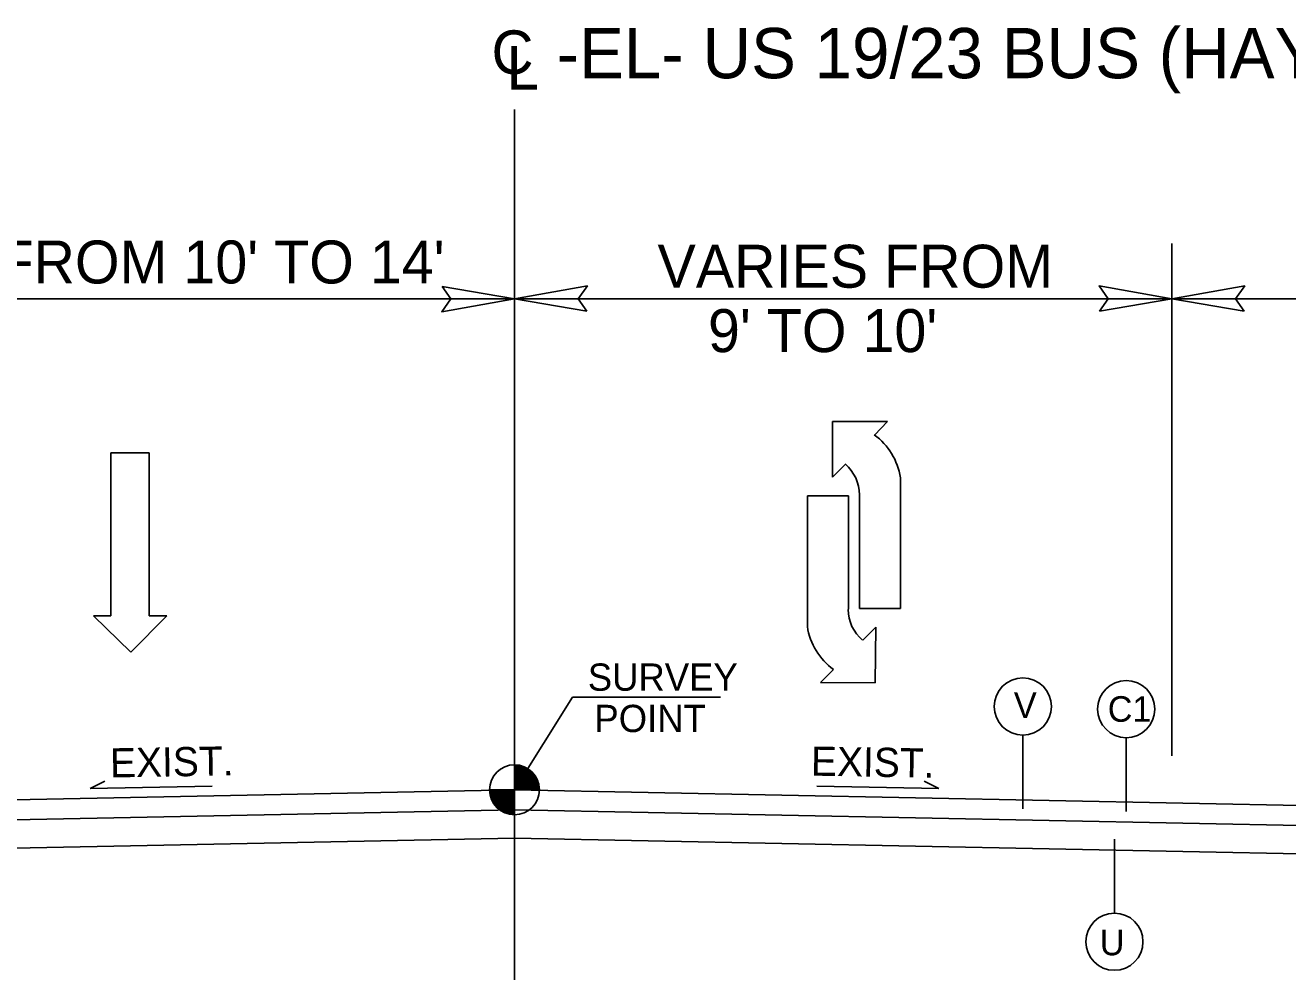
# Model space of a CAD drawing. Extents: x 1022283 to 1026986, y 174822 to 180471.
# Drawn here: x 1023625.2 to 1024095.7, y 178947.4 to 179303 of the extents above; entities that cross this region are included whole.
import ezdxf

# ---------------------------------------------------------------- set-up
doc = ezdxf.new("R2010")
doc.units = 0
for name, color, linetype in [('Default', 7, 'Continuous'), ('Prop Dimension', 7, 'Continuous'), ('Prop Lane Arrow CELL', 7, 'Continuous'), ('Prop Terminator CELL', 7, 'Continuous'), ('Typical Berm Information CELL', 7, 'Continuous'), ('Typical Grade Point Symbol CELL', 7, 'Continuous'), ('Typical ID Circle CELL', 7, 'Continuous'), ('Typical Text Centerline CELL', 7, 'Continuous'), ('Typical Text Grade Point CELL', 7, 'Continuous'), ('Typical Text ID Circle CELL', 7, 'Continuous')]:
    doc.layers.add(name, color=color, linetype=linetype)

# ---------------------------------------------------------------- blocks, each defined once
blk = doc.blocks.new('Lane Arrow Through')
at = {"layer": 'Prop Lane Arrow CELL'}
for p, q in [((-3.15, 1.6), (-3.15, 3.1)), ((-3.15, 3.1), (0, 0)), ((-17.15, 1.6), (-3.15, 1.6)), ((-17.15, -1.7), (-17.15, 1.6)), ((0, 0), (-3.15, -3.2)), ((-3.15, -1.7), (-17.15, -1.7)), ((-3.15, -3.2), (-3.15, -1.7))]:
    blk.add_line(p, q, dxfattribs=at)

msp = doc.modelspace()

# ---------------------------------------------------------------- linework, layer by layer
at = {"layer": 'Default'}
for p, q in [((1024052.49, 179030.88), (1024052.49, 179221.7)), ((1023299.79, 179201.13), (1023807.5, 179201.13)), ((1023807.5, 179201.13), (1024315.21, 179201.13)), ((1024315.21, 179201.13), (1023807.5, 179201.13))]:
    msp.add_line(p, q, dxfattribs=at)
at = {"layer": 'Prop Dimension'}
for p, q in [((1023807.5, 179212.25), (1023807.5, 179271.7)), ((1023807.5, 178947.45), (1023807.5, 179212.25)), ((1023829.15, 179052.68), (1023807.5, 179018.24)), ((1023829.15, 179052.68), (1023807.5, 179018.24)), ((1023312.45, 179008.34), (1023807.5, 179018.24)), ((1023312.45, 179008.34), (1023807.5, 179018.24)), ((1024315.21, 179008.08), (1023807.5, 179018.24)), ((1024315.21, 179008.08), (1023807.5, 179018.24)), ((1023312.45, 179000.84), (1023807.5, 179010.74)), ((1023312.45, 179000.84), (1023807.5, 179010.74)), ((1024315.21, 179000.58), (1023807.5, 179010.74)), ((1024315.21, 179000.58), (1023807.5, 179010.74)), ((1023299.79, 178990), (1023807.5, 179000.15)), ((1024315.21, 178990), (1023807.5, 179000.15))]:
    msp.add_line(p, q, dxfattribs=at)
at = {"layer": 'Prop Lane Arrow CELL'}
for p, q in [((1023946.5, 179155.44), (1023925.95, 179155.44)), ((1023925.95, 179155.44), (1023925.95, 179134.66)), ((1023941.65, 179150.36), (1023946.5, 179155.44)), ((1023925.95, 179134.66), (1023930.8, 179139.51)), ((1023951.35, 179085.72), (1023951.35, 179134.43)), ((1023916.72, 179127.74), (1023916.72, 179079.02)), ((1023931.96, 179127.74), (1023916.72, 179127.74)), ((1023931.96, 179085.48), (1023931.96, 179127.74)), ((1023931.96, 179127.74), (1023931.96, 179085.48)), ((1023936.11, 179127.97), (1023936.11, 179085.72)), ((1023936.11, 179085.72), (1023951.35, 179085.72)), ((1023942.12, 179078.79), (1023937.27, 179073.94)), ((1023941.88, 179058.01), (1023942.12, 179078.79)), ((1023926.41, 179063.09), (1023921.57, 179058.24)), ((1023921.57, 179058.24), (1023941.88, 179058.01))]:
    msp.add_line(p, q, dxfattribs=at)
for centre, radius, start, end in [((1023927.32, 179130.84), 24.26, 8.6761, 53.9878), ((1023920.93, 179128.08), 15.12, 360, 49.6582), ((1023947, 179085.44), 15.12, 180, 229.6582), ((1023940.62, 179082.68), 24.26, 188.6761, 233.9878)]:
    msp.add_arc(centre, radius, start, end, dxfattribs=at)
at = {"layer": 'Prop Terminator CELL'}
for points in [[(1023780.5, 179205.78), (1023807.5, 179201.13), (1023780.35, 179196.33), (1023783.8, 179201.13)], [(1023834.5, 179196.48), (1023807.5, 179201.13), (1023834.65, 179205.93), (1023831.2, 179201.13)], [(1023834.5, 179196.48), (1023807.5, 179201.13), (1023834.65, 179205.93), (1023831.2, 179201.13)], [(1024025.49, 179196.48), (1024052.49, 179201.13), (1024025.34, 179205.93), (1024028.79, 179201.13)], [(1024079.49, 179196.48), (1024052.49, 179201.13), (1024079.64, 179205.93), (1024076.19, 179201.13)]]:
    msp.add_lwpolyline(points, close=True, dxfattribs=at)
at = {"layer": 'Typical Berm Information CELL'}
for p, q in [((1023654.85, 179021.45), (1023649.33, 179018.68)), ((1023960.16, 179021.45), (1023965.68, 179018.68)), ((1023649.33, 179018.68), (1023694.85, 179019.6)), ((1023965.68, 179018.68), (1023920.16, 179019.6))]:
    msp.add_line(p, q, dxfattribs=at)
at = {"layer": 'Typical Grade Point Symbol CELL'}
for p, q in [((1023807.5, 179018.24), (1023807.5, 179027.53)), ((1023807.5, 179018.24), (1023807.5, 179027.53)), ((1023798.21, 179018.24), (1023807.5, 179018.24)), ((1023798.21, 179018.24), (1023807.5, 179018.24)), ((1023807.48, 179008.94), (1023807.5, 179018.24)), ((1023807.5, 179018.24), (1023807.48, 179008.94)), ((1023807.48, 179008.94), (1023807.5, 179018.24)), ((1023807.5, 179018.24), (1023807.48, 179008.94)), ((1023816.8, 179018.24), (1023807.5, 179018.24)), ((1023816.8, 179018.24), (1023807.5, 179018.24))]:
    msp.add_line(p, q, dxfattribs=at)
for points in [[(1023807.59, 179027.53), (1023807.59, 179027.53), (1023807.59, 179018.24)], [(1023807.59, 179027.53), (1023807.59, 179027.53), (1023807.59, 179018.24)], [(1023807.77, 179027.53), (1023807.77, 179018.24)], [(1023807.77, 179027.53), (1023807.77, 179018.24)], [(1023807.96, 179027.51), (1023807.96, 179018.24)], [(1023807.96, 179027.51), (1023807.96, 179018.24)], [(1023808.14, 179027.51), (1023808.14, 179018.24)], [(1023808.14, 179027.51), (1023808.14, 179018.24)], [(1023808.33, 179027.49), (1023808.33, 179018.24)], [(1023808.33, 179027.49), (1023808.33, 179018.24)], [(1023808.52, 179027.47), (1023808.52, 179018.24)], [(1023808.52, 179027.47), (1023808.52, 179018.24)], [(1023808.7, 179027.45), (1023808.7, 179018.24)], [(1023808.7, 179027.45), (1023808.7, 179018.24)], [(1023808.89, 179027.43), (1023808.89, 179018.24)], [(1023808.89, 179027.43), (1023808.89, 179018.24)], [(1023809.07, 179027.41), (1023809.07, 179018.24)], [(1023809.07, 179027.41), (1023809.07, 179018.24)], [(1023809.26, 179027.37), (1023809.26, 179018.24)], [(1023809.26, 179027.37), (1023809.26, 179018.24)], [(1023809.45, 179027.33), (1023809.45, 179018.24)], [(1023809.45, 179027.33), (1023809.45, 179018.24)], [(1023809.63, 179027.29), (1023809.63, 179018.24)], [(1023809.63, 179027.29), (1023809.63, 179018.24)], [(1023809.82, 179027.25), (1023809.82, 179018.24)], [(1023809.82, 179027.25), (1023809.82, 179018.24)], [(1023810, 179027.18), (1023810, 179018.24)], [(1023810, 179027.18), (1023810, 179018.24)], [(1023810.19, 179027.14), (1023810.19, 179018.24)], [(1023810.19, 179027.14), (1023810.19, 179018.24)], [(1023810.38, 179027.08), (1023810.38, 179018.24)], [(1023810.38, 179027.08), (1023810.38, 179018.24)], [(1023810.56, 179027.02), (1023810.56, 179018.24)], [(1023810.56, 179027.02), (1023810.56, 179018.24)], [(1023810.75, 179026.96), (1023810.75, 179018.24)], [(1023810.75, 179026.96), (1023810.75, 179018.24)], [(1023810.93, 179026.87), (1023810.93, 179018.24)], [(1023810.93, 179026.87), (1023810.93, 179018.24)], [(1023811.12, 179026.79), (1023811.12, 179018.24)], [(1023811.12, 179026.79), (1023811.12, 179018.24)], [(1023811.31, 179026.71), (1023811.31, 179018.24)], [(1023811.31, 179026.71), (1023811.31, 179018.24)], [(1023811.49, 179026.63), (1023811.49, 179018.24)], [(1023811.49, 179026.63), (1023811.49, 179018.24)], [(1023811.68, 179026.54), (1023811.68, 179018.24)], [(1023811.68, 179026.54), (1023811.68, 179018.24)], [(1023811.86, 179026.44), (1023811.86, 179018.24)], [(1023811.86, 179026.44), (1023811.86, 179018.24)], [(1023812.05, 179026.34), (1023812.05, 179018.24)], [(1023812.05, 179026.34), (1023812.05, 179018.24)], [(1023812.23, 179026.23), (1023812.23, 179018.24)], [(1023812.23, 179026.23), (1023812.23, 179018.24)], [(1023812.42, 179026.13), (1023812.42, 179018.24)], [(1023812.42, 179026.13), (1023812.42, 179018.24)], [(1023812.61, 179026.01), (1023812.61, 179018.24)], [(1023812.61, 179026.01), (1023812.61, 179018.24)], [(1023812.79, 179025.88), (1023812.79, 179018.24)], [(1023812.79, 179025.88), (1023812.79, 179018.24)], [(1023812.98, 179025.74), (1023812.98, 179018.24)], [(1023812.98, 179025.74), (1023812.98, 179018.24)], [(1023813.16, 179025.61), (1023813.16, 179018.24)], [(1023813.16, 179025.61), (1023813.16, 179018.24)], [(1023813.35, 179025.47), (1023813.35, 179018.24)], [(1023813.35, 179025.47), (1023813.35, 179018.24)], [(1023813.54, 179025.3), (1023813.54, 179018.24)], [(1023813.54, 179025.3), (1023813.54, 179018.24)], [(1023813.72, 179025.14), (1023813.72, 179018.24)], [(1023813.72, 179025.14), (1023813.72, 179018.24)], [(1023813.91, 179024.97), (1023813.91, 179018.24)], [(1023813.91, 179024.97), (1023813.91, 179018.24)], [(1023814.09, 179024.79), (1023814.09, 179018.24)], [(1023814.09, 179024.79), (1023814.09, 179018.24)], [(1023814.28, 179024.6), (1023814.28, 179018.24)], [(1023814.28, 179024.6), (1023814.28, 179018.24)], [(1023814.47, 179024.39), (1023814.47, 179018.24)], [(1023814.47, 179024.39), (1023814.47, 179018.24)], [(1023814.65, 179024.17), (1023814.65, 179018.24)], [(1023814.65, 179024.17), (1023814.65, 179018.24)], [(1023814.84, 179023.94), (1023814.84, 179018.24)], [(1023814.84, 179023.94), (1023814.84, 179018.24)], [(1023815.02, 179023.69), (1023815.02, 179018.24)], [(1023815.02, 179023.69), (1023815.02, 179018.24)], [(1023815.21, 179023.42), (1023815.21, 179018.24)], [(1023815.21, 179023.42), (1023815.21, 179018.24)], [(1023815.4, 179023.13), (1023815.4, 179018.24)], [(1023815.4, 179023.13), (1023815.4, 179018.24)], [(1023815.58, 179022.83), (1023815.58, 179018.24)], [(1023815.58, 179022.83), (1023815.58, 179018.24)], [(1023815.77, 179022.49), (1023815.77, 179018.24)], [(1023815.77, 179022.49), (1023815.77, 179018.24)], [(1023815.95, 179022.1), (1023815.95, 179018.24)], [(1023815.95, 179022.1), (1023815.95, 179018.24)], [(1023816.14, 179021.67), (1023816.14, 179018.24)], [(1023816.14, 179021.67), (1023816.14, 179018.24)], [(1023816.32, 179021.15), (1023816.32, 179018.24)], [(1023816.32, 179021.15), (1023816.32, 179018.24)], [(1023798.25, 179018.24), (1023798.25, 179017.23)], [(1023798.25, 179018.24), (1023798.25, 179017.23)], [(1023798.44, 179018.24), (1023798.44, 179016.13)], [(1023798.44, 179018.24), (1023798.44, 179016.13)], [(1023798.62, 179018.24), (1023798.62, 179015.47)], [(1023798.62, 179018.24), (1023798.62, 179015.47)], [(1023798.81, 179018.24), (1023798.81, 179014.91)], [(1023798.81, 179018.24), (1023798.81, 179014.91)], [(1023798.99, 179018.24), (1023798.99, 179014.48)], [(1023798.99, 179018.24), (1023798.99, 179014.48)], [(1023799.18, 179018.24), (1023799.18, 179014.09)], [(1023799.18, 179018.24), (1023799.18, 179014.09)], [(1023799.37, 179018.24), (1023799.37, 179013.74)], [(1023799.37, 179018.24), (1023799.37, 179013.74)], [(1023799.55, 179018.24), (1023799.55, 179013.41)], [(1023799.55, 179018.24), (1023799.55, 179013.41)], [(1023799.74, 179018.24), (1023799.74, 179013.12)], [(1023799.74, 179018.24), (1023799.74, 179013.12)], [(1023799.92, 179018.24), (1023799.92, 179012.85)], [(1023799.92, 179018.24), (1023799.92, 179012.85)], [(1023800.11, 179018.24), (1023800.11, 179012.6)], [(1023800.11, 179018.24), (1023800.11, 179012.6)], [(1023800.3, 179018.24), (1023800.3, 179012.37)], [(1023800.3, 179018.24), (1023800.3, 179012.37)], [(1023800.48, 179018.24), (1023800.48, 179012.15)], [(1023800.48, 179018.24), (1023800.48, 179012.15)], [(1023800.67, 179018.24), (1023800.67, 179011.94)], [(1023800.67, 179018.24), (1023800.67, 179011.94)], [(1023800.85, 179018.24), (1023800.85, 179011.73)], [(1023800.85, 179018.24), (1023800.85, 179011.73)], [(1023801.04, 179018.24), (1023801.04, 179011.55)], [(1023801.04, 179018.24), (1023801.04, 179011.55)], [(1023801.23, 179018.24), (1023801.23, 179011.38)], [(1023801.23, 179018.24), (1023801.23, 179011.38)], [(1023801.41, 179018.24), (1023801.41, 179011.22)], [(1023801.41, 179018.24), (1023801.41, 179011.22)], [(1023801.6, 179018.24), (1023801.6, 179011.05)], [(1023801.6, 179018.24), (1023801.6, 179011.05)], [(1023801.78, 179018.24), (1023801.78, 179010.91)], [(1023801.78, 179018.24), (1023801.78, 179010.91)], [(1023801.97, 179018.24), (1023801.97, 179010.76)], [(1023801.97, 179018.24), (1023801.97, 179010.76)], [(1023802.15, 179018.24), (1023802.15, 179010.64)], [(1023802.15, 179018.24), (1023802.15, 179010.64)], [(1023802.34, 179018.24), (1023802.34, 179010.51)], [(1023802.34, 179018.24), (1023802.34, 179010.51)], [(1023802.53, 179018.24), (1023802.53, 179010.39)], [(1023802.53, 179018.24), (1023802.53, 179010.39)], [(1023802.71, 179018.24), (1023802.71, 179010.27)], [(1023802.71, 179018.24), (1023802.71, 179010.27)], [(1023802.9, 179018.24), (1023802.9, 179010.16)], [(1023802.9, 179018.24), (1023802.9, 179010.16)], [(1023803.08, 179018.24), (1023803.08, 179010.06)], [(1023803.08, 179018.24), (1023803.08, 179010.06)], [(1023803.27, 179018.24), (1023803.27, 179009.96)], [(1023803.27, 179018.24), (1023803.27, 179009.96)], [(1023803.46, 179018.24), (1023803.46, 179009.87)], [(1023803.46, 179018.24), (1023803.46, 179009.87)], [(1023803.64, 179018.24), (1023803.64, 179009.79)], [(1023803.64, 179018.24), (1023803.64, 179009.79)], [(1023803.83, 179018.24), (1023803.83, 179009.71)], [(1023803.83, 179018.24), (1023803.83, 179009.71)], [(1023804.01, 179018.24), (1023804.01, 179009.63)], [(1023804.01, 179018.24), (1023804.01, 179009.63)], [(1023804.2, 179018.24), (1023804.2, 179009.54)], [(1023804.2, 179018.24), (1023804.2, 179009.54)], [(1023804.39, 179018.24), (1023804.39, 179009.48)], [(1023804.39, 179018.24), (1023804.39, 179009.48)], [(1023804.57, 179018.24), (1023804.57, 179009.42)], [(1023804.57, 179018.24), (1023804.57, 179009.42)], [(1023804.76, 179018.24), (1023804.76, 179009.36)], [(1023804.76, 179018.24), (1023804.76, 179009.36)], [(1023804.94, 179018.24), (1023804.94, 179009.32)], [(1023804.94, 179018.24), (1023804.94, 179009.32)], [(1023805.13, 179018.24), (1023805.13, 179009.25)], [(1023805.13, 179018.24), (1023805.13, 179009.25)], [(1023805.32, 179018.24), (1023805.32, 179009.21)], [(1023805.32, 179018.24), (1023805.32, 179009.21)], [(1023805.5, 179018.24), (1023805.5, 179009.17)], [(1023805.5, 179018.24), (1023805.5, 179009.17)], [(1023805.69, 179018.24), (1023805.69, 179009.13)], [(1023805.69, 179018.24), (1023805.69, 179009.13)], [(1023805.87, 179018.24), (1023805.87, 179009.09)], [(1023805.87, 179018.24), (1023805.87, 179009.09)], [(1023806.06, 179018.24), (1023806.06, 179009.07)], [(1023806.06, 179018.24), (1023806.06, 179009.07)], [(1023806.24, 179018.24), (1023806.24, 179009.03)], [(1023806.24, 179018.24), (1023806.24, 179009.03)], [(1023806.43, 179018.24), (1023806.43, 179009.01)], [(1023806.43, 179018.24), (1023806.43, 179009.01)], [(1023806.62, 179018.24), (1023806.62, 179008.99)], [(1023806.62, 179018.24), (1023806.62, 179008.99)], [(1023806.8, 179018.24), (1023806.8, 179008.96)], [(1023806.8, 179018.24), (1023806.8, 179008.96)], [(1023806.99, 179018.24), (1023806.99, 179008.96)], [(1023806.99, 179018.24), (1023806.99, 179008.96)], [(1023807.17, 179018.24), (1023807.17, 179008.94)], [(1023807.17, 179018.24), (1023807.17, 179008.94)], [(1023807.36, 179018.24), (1023807.36, 179008.94), (1023807.36, 179008.94)], [(1023807.36, 179018.24), (1023807.36, 179008.94), (1023807.36, 179008.94)], [(1023816.51, 179020.51), (1023816.51, 179018.24)], [(1023816.51, 179020.51), (1023816.51, 179018.24)], [(1023816.7, 179019.56), (1023816.7, 179018.24)], [(1023816.7, 179019.56), (1023816.7, 179018.24)]]:
    msp.add_lwpolyline(points, dxfattribs=at)
msp.add_circle((1023807.49, 179018.24), 9.3, dxfattribs=at)
msp.add_circle((1023807.49, 179018.24), 9.3, dxfattribs=at)
for start, end in [(359.9905, 89.9905), (359.9905, 89.9905), (179.9905, 269.9905), (179.9905, 269.9905)]:
    msp.add_arc((1023807.49, 179018.24), 9.3, start, end, dxfattribs=at)
at = {"layer": 'Typical ID Circle CELL'}
for p, q in [((1023996.95, 179038.6), (1023996.95, 179011.07)), ((1024035.48, 179037.63), (1024035.48, 179010.11)), ((1024031.08, 178972.27), (1024031.08, 178999.8))]:
    msp.add_line(p, q, dxfattribs=at)
for centre in [(1023996.95, 179049.24), (1024035.48, 179048.28), (1024031.08, 178961.62)]:
    msp.add_circle(centre, 10.65, dxfattribs=at)
at = {"layer": 'Typical Text Grade Point CELL'}
msp.add_line((1023829.15, 179052.68), (1023884.26, 179052.68), dxfattribs=at)

# ---------------------------------------------------------------- block references
at = {"layer": 'Prop Lane Arrow CELL', "xscale": 4.329849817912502, "yscale": 4.3298498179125, "rotation": -89.99999999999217}
msp.add_blockref('Lane Arrow Through', (1023664.46, 179069.44), dxfattribs=at)

# ---------------------------------------------------------------- texts
at = {"layer": 'Prop Dimension'}
for s, height, p in [('-EL- US 19/23 BUS (HAYWOOD RD) ', 18.75, (1023823.22, 179283.3)), ("VARIES FROM 10' TO 14'", 16, (1023530.73, 179206.85)), ('VARIES FROM', 16, (1023860.8, 179205.28)), ("9' TO 10'", 16, (1023879.6, 179181.28))]:
    msp.add_text(s, height=height, dxfattribs=at).set_placement(p)
at = {"layer": 'Typical Berm Information CELL'}
for rotation, p in [(0.9927, (1023656.82, 179022.79)), (359.0073, (1023917.9, 179023.49))]:
    msp.add_text('EXIST.', height=10.873, rotation=rotation, dxfattribs=at).set_placement(p)
at = {"layer": 'Typical Text Centerline CELL'}
msp.add_text('C', height=16.22, dxfattribs=at).set_placement((1023798.92, 179284.91))
msp.add_text('L', height=16.22, rotation=359.9469, dxfattribs=at).set_placement((1023804.58, 179279.1))
at = {"layer": 'Typical Text Grade Point CELL'}
for s, p in [('SURVEY', (1023834.82, 179055.11)), ('POINT', (1023837.27, 179039.71))]:
    msp.add_text(s, height=10.163, dxfattribs=at).set_placement(p)
at = {"layer": 'Typical Text ID Circle CELL'}
for s, height, p in [('V', 9.53, (1023993.6, 179044.94)), ('C1', 9.534, (1024028.59, 179043.55)), ('U', 9.53, (1024025.63, 178956.56))]:
    msp.add_text(s, height=height, dxfattribs=at).set_placement(p)

doc.saveas('drawing.dxf')
